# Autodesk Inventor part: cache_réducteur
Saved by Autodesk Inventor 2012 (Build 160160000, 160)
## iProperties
Created: 2013-08
Part Number: cache_réducteur
Material: Default
Document SubType Name: Modeling
Designer: hilarion
Density: 1 g/cm^3
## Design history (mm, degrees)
node "cache_réducteur1"
node "cache_réducteur"
node "Base1"
